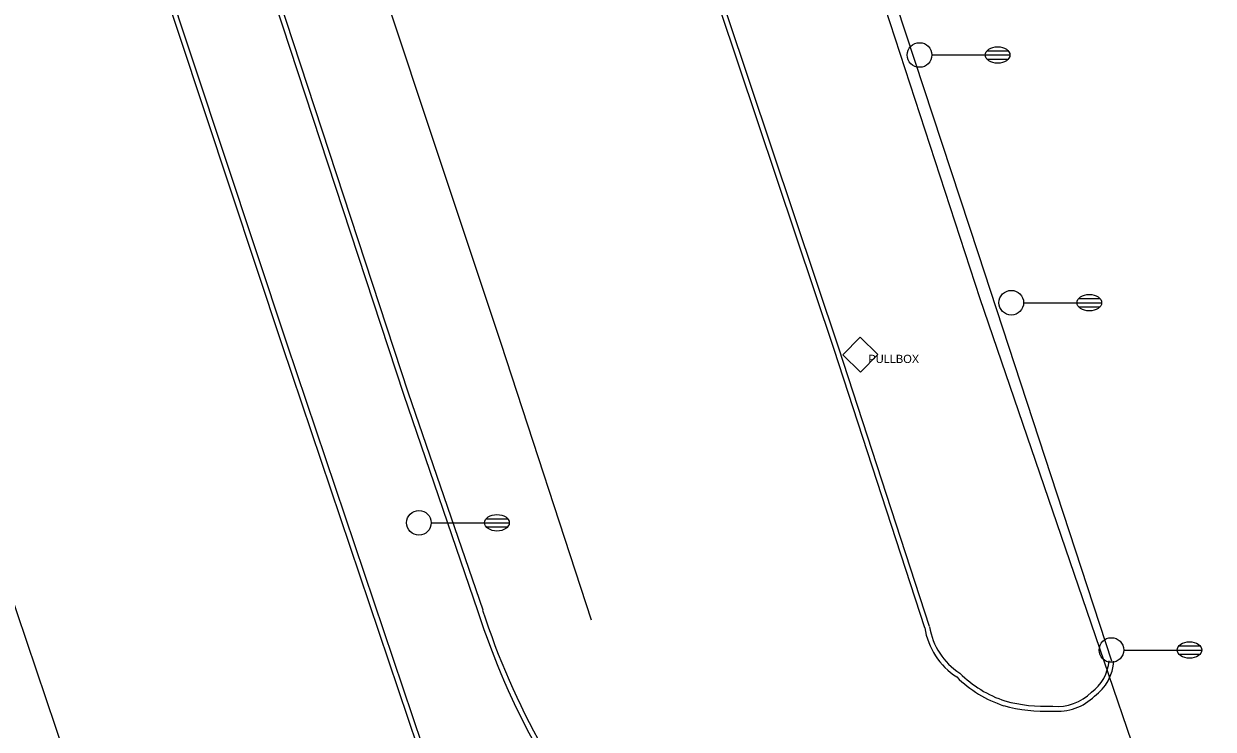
# Model space of a CAD drawing. Extents: x 2145380 to 2157287, y 139568 to 149130.
# Drawn here: x 2147392.4 to 2147537.1, y 142759 to 142844.8 of the extents above; entities that cross this region are included whole.
import ezdxf

# ---------------------------------------------------------------- set-up
doc = ezdxf.new("R2010")
doc.units = 0
for name, color, linetype in [('Default', 7, 'Continuous'), ('TOPO_Asphalt', 7, 'Continuous'), ('TOPO_Curb Back', 7, 'Continuous'), ('TOPO_Fence', 7, 'Continuous'), ('TOPO_Guardrail', 7, 'Continuous'), ('TOPO_Light Pole', 7, 'Continuous'), ('TOPO_Misc Line', 7, 'Continuous'), ('TOPO_Power Pullbox', 7, 'Continuous')]:
    doc.layers.add(name, color=color, linetype=linetype)

# ---------------------------------------------------------------- blocks, each defined once
blk = doc.blocks.new('LP')
at = {"layer": 'TOPO_Light Pole'}
blk.add_line((3.81, 0), (20.32, 0), dxfattribs=at)
for points in [[(20.32, 0), (27.94, 0)], [(20.32, 0), (23.5, 0)], [(20.83, 1.27), (27.43, 1.27)], [(20.83, 1.27), (23.5, 1.27)], [(23.71, 1.27), (27.43, 1.27)], [(23.71, 0), (27.94, 0)], [(20.83, -1.27), (27.43, -1.27)], [(20.83, -1.27), (23.5, -1.27)], [(23.71, -1.27), (27.43, -1.27)]]:
    blk.add_lwpolyline(points, dxfattribs=at)
blk.add_circle((0, 0), 3.81, dxfattribs=at)
blk.add_ellipse((24.13, 0), major_axis=(3.81, 0), ratio=0.666667, dxfattribs=at)
blk = doc.blocks.new('pulbox')
at = {"layer": 'Default'}
blk.add_lwpolyline([(-5.38, -0.01), (-0.02, 5.42), (5.4, 0.06), (0.05, -5.36), (-5.38, -0.01)], dxfattribs=at)
blk.add_text('PULLBOX', height=2.54, dxfattribs=at).set_placement((2.54, -2.54))

msp = doc.modelspace()

# ---------------------------------------------------------------- linework, layer by layer
at = {"layer": 'TOPO_Asphalt'}
msp.add_line((2147379.12, 142809.78), (2147402.56, 142740.4), dxfattribs=at)
msp.add_lwpolyline([(2147496.3, 142853.83), (2147508.5, 142816.84), (2147524.71, 142767.27)], dxfattribs=at)
at = {"layer": 'TOPO_Curb Back'}
for points in [[(2147406.51, 142898.82), (2147409.49, 142891.14), (2147421.62, 142853.31), (2147439.11, 142799.9), (2147448.19, 142773.47)], [(2147405.97, 142898.56), (2147408.92, 142890.94), (2147421.05, 142853.12), (2147438.54, 142799.71), (2147447.62, 142773.28)], [(2147459.61, 142697.37), (2147440.29, 142756.78), (2147423.84, 142805.62), (2147404.95, 142862.58), (2147403, 142867.87), (2147393.71, 142894.97)], [(2147460.18, 142697.55), (2147440.86, 142756.97), (2147424.41, 142805.81), (2147405.51, 142862.78), (2147403.56, 142868.07), (2147394.27, 142895.2)], [(2147501.98, 142771.3), (2147490.97, 142805.16), (2147474.68, 142853.73), (2147468.3, 142872.71)], [(2147502.56, 142771.44), (2147491.54, 142805.34), (2147475.25, 142853.92), (2147468.78, 142873.16)]]:
    msp.add_lwpolyline(points, dxfattribs=at)
for centre, radius, start, end in [((2147535.4, 142801.47), 92.2, 197.8061, 209.1932), ((2147535.4, 142801.47), 91.6, 197.8023, 209.2021), ((2147510.72, 142772.73), 8.86, 189.331, 236.8), ((2147510.72, 142772.73), 8.26, 189.0201, 237.2141), ((2147519.18, 142767.71), 5.25, 305.8611, 355.4185), ((2147519.18, 142767.71), 5.85, 306.3459, 355.4185), ((2147516.23, 142775.81), 14.14, 225.12, 251.5083), ((2147516.23, 142775.81), 14.74, 225.3652, 251.5748), ((2147518.14, 142767.53), 6.39, 264.5901, 314.8334), ((2147518.14, 142767.53), 5.79, 264.1792, 315.2752), ((2147516.65, 142780.44), 19.29, 254.7158, 272.6403), ((2147516.65, 142780.44), 18.69, 254.7663, 272.7719)]:
    msp.add_arc(centre, radius, start, end, dxfattribs=at)
at = {"layer": 'TOPO_Fence'}
msp.add_line((2147537.08, 142728.5), (2147523.83, 142767.24), dxfattribs=at)
at = {"layer": 'TOPO_Guardrail'}
msp.add_lwpolyline([(2147523.83, 142767.24), (2147508.72, 142811.35), (2147494.73, 142854.27), (2147526.91, 142861.94), (2147533.09, 142871.32), (2147527.13, 142907.57)], dxfattribs=at)
at = {"layer": 'TOPO_Misc Line'}
msp.add_lwpolyline([(2147419.65, 142898.98), (2147428.48, 142871.71), (2147450.39, 142805.93), (2147461.38, 142772.28)], dxfattribs=at)

# ---------------------------------------------------------------- block references
at = {"layer": 'TOPO_Light Pole', "xscale": 0.39370000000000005, "yscale": 0.3937000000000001}
for p in [(2147501.35, 142841), (2147512.51, 142810.86), (2147440.43, 142784.08), (2147524.7, 142768.6)]:
    msp.add_blockref('LP', p, dxfattribs=at)
at = {"layer": 'TOPO_Power Pullbox', "xscale": 0.39370000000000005, "yscale": 0.3937000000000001}
msp.add_blockref('pulbox', (2147494.13, 142804.52), dxfattribs=at)

doc.saveas('drawing.dxf')
